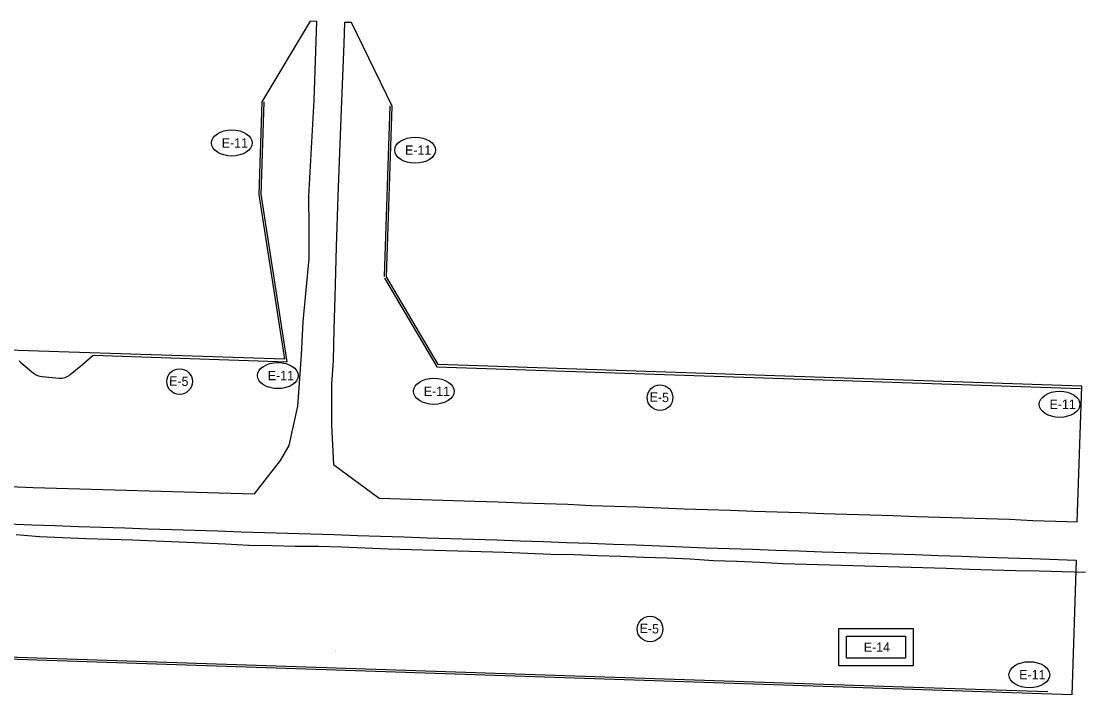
# Model space of a CAD drawing. Extents: x 977239 to 983725, y 1525948 to 1526901.
# Drawn here: x 978169 to 978854, y 1526369 to 1526803 of the extents above; entities that cross this region are included whole.
import ezdxf

# ---------------------------------------------------------------- set-up
doc = ezdxf.new("R2010")
doc.units = 0
for name, color, linetype in [('R_Erosion', 7, 'Continuous'), ('R_No Plot', 7, 'Continuous'), ('R_Water', 7, 'Continuous')]:
    doc.layers.add(name, color=color, linetype=linetype)

msp = doc.modelspace()

# ---------------------------------------------------------------- linework, layer by layer
at = {"layer": 'R_Erosion'}
for p, q in [((978323.31, 1526691.17), (978325.31, 1526751.13)), ((978406.27, 1526748.43), (978402.59, 1526638.49)), ((978340.18, 1526583.6), (978323.29, 1526691.54)), ((978402.87, 1526637.4), (978436.57, 1526580.37)), ((978168.64, 1526582.83), (978176.48, 1526576.28)), ((978215.04, 1526587.8), (978340.18, 1526583.6)), ((978200.27, 1526575.28), (978208.1, 1526581.74)), ((978436.57, 1526580.37), (978851.75, 1526566.46)), ((978182.02, 1526574), (978193.03, 1526573.03)), ((978128.43, 1526394.59), (978743.95, 1526373.96)), ((978743.95, 1526373.96), (978830.77, 1526371.05))]:
    msp.add_line(p, q, dxfattribs=at)
msp.add_lwpolyline([(978208.32, 1526581.93), (978215.04, 1526587.8)], dxfattribs=at)
for points in [[(978695.81, 1526411.68), (978743.81, 1526411.7), (978743.81, 1526387.7), (978695.81, 1526387.68)], [(978700.81, 1526406.68), (978738.81, 1526406.7), (978738.81, 1526392.7), (978700.81, 1526392.68)]]:
    msp.add_lwpolyline(points, close=True, dxfattribs=at)
for centre in [(978270.74, 1526570.81), (978580.61, 1526560.44), (978574.17, 1526411.38)]:
    msp.add_circle(centre, 8.26, dxfattribs=at)
for centre, start, end in [((978175.04, 1526590.51), 218.29041, 230.15852), ((978182.89, 1526583.96), 230.15852, 264.99974), ((978201.74, 1526589.46), 309.51371, 311.152), ((978193.91, 1526583), 264.99974, 309.51371)]:
    msp.add_arc(centre, 10, start, end, dxfattribs=at)
for centre in [(978304.42, 1526724.55), (978422.62, 1526719.89), (978334.1, 1526574.66), (978434.71, 1526564.55), (978838.25, 1526556.17), (978818.73, 1526381.9)]:
    msp.add_ellipse(centre, major_axis=(13.15, 0), ratio=0.638788, dxfattribs=at)
at = {"layer": 'R_No Plot'}
for p, q in [((978355.02, 1526802.97), (978323.81, 1526751.05)), ((978359.16, 1526802.84), (978355.02, 1526802.97)), ((978381.56, 1526802.09), (978377.18, 1526802.23)), ((978407.76, 1526748.25), (978381.56, 1526802.09)), ((978323.81, 1526751.05), (978321.81, 1526691.26)), ((978404.09, 1526638.29), (978407.76, 1526748.25)), ((978321.81, 1526691.26), (978338.42, 1526585.16)), ((978437.45, 1526581.84), (978404.09, 1526638.29)), ((978338.42, 1526585.16), (978136.55, 1526591.93)), ((978852.61, 1526567.93), (978437.45, 1526581.84)), ((978849.68, 1526480.46), (978852.61, 1526567.93)), ((978161.38, 1526503.3), (978176.36, 1526502.64)), ((978176.36, 1526502.64), (978191.36, 1526502.23)), ((978191.36, 1526502.23), (978206.35, 1526501.67)), ((978206.35, 1526501.67), (978221.34, 1526501.21)), ((978221.34, 1526501.21), (978236.2, 1526500.8)), ((978236.2, 1526500.8), (978251.19, 1526500.38)), ((978251.19, 1526500.38), (978266.19, 1526499.97)), ((978266.19, 1526499.97), (978281.18, 1526499.46)), ((978281.18, 1526499.46), (978319.1, 1526498.58)), ((978399.47, 1526495.75), (978461.18, 1526493.66)), ((978461.18, 1526493.66), (978476.18, 1526493.23)), ((978476.18, 1526493.23), (978491.17, 1526492.72)), ((978491.17, 1526492.72), (978506.16, 1526492.22)), ((978506.16, 1526492.22), (978521.15, 1526491.72)), ((978521.15, 1526491.72), (978536.14, 1526491.07)), ((978536.14, 1526491.07), (978551.13, 1526490.56)), ((978551.13, 1526490.56), (978566.12, 1526490.06)), ((978566.12, 1526490.06), (978581.11, 1526489.47)), ((978581.11, 1526489.47), (978596.14, 1526488.92)), ((978596.14, 1526488.92), (978611.13, 1526488.49)), ((978611.13, 1526488.49), (978626.12, 1526487.94)), ((978626.12, 1526487.94), (978641.11, 1526487.37)), ((978641.11, 1526487.37), (978656.11, 1526486.91)), ((978656.11, 1526486.91), (978671.1, 1526486.38)), ((978671.1, 1526486.38), (978686.02, 1526485.87)), ((978686.02, 1526485.87), (978701.01, 1526485.39)), ((978701.01, 1526485.39), (978716, 1526484.91)), ((978716, 1526484.91), (978731, 1526484.43)), ((978731, 1526484.43), (978745.99, 1526483.96)), ((978745.99, 1526483.96), (978760.98, 1526483.48)), ((978760.98, 1526483.48), (978775.97, 1526483)), ((978775.97, 1526483), (978790.96, 1526482.53)), ((978790.96, 1526482.53), (978805.96, 1526482.06)), ((978805.96, 1526482.06), (978820.94, 1526481.37)), ((978820.94, 1526481.37), (978835.93, 1526480.9)), ((978835.93, 1526480.9), (978849.68, 1526480.46)), ((978160.49, 1526479.09), (978175.48, 1526478.58)), ((978175.48, 1526478.58), (978190.47, 1526478.02)), ((978190.47, 1526478.02), (978205.46, 1526477.46)), ((978205.46, 1526477.46), (978220.45, 1526476.94)), ((978220.45, 1526476.94), (978235.54, 1526476.48)), ((978235.54, 1526476.48), (978250.54, 1526476.02)), ((978250.54, 1526476.02), (978265.53, 1526475.57)), ((978265.53, 1526475.57), (978280.52, 1526475.09)), ((978280.52, 1526475.09), (978295.51, 1526474.59)), ((978295.51, 1526474.59), (978310.5, 1526474.06)), ((978310.5, 1526474.06), (978325.48, 1526473.61)), ((978325.48, 1526473.61), (978340.47, 1526473.18)), ((978340.47, 1526473.18), (978355.46, 1526472.68)), ((978355.46, 1526472.68), (978370.45, 1526472.2)), ((978165.3, 1526472.32), (978180.33, 1526470.98)), ((978180.33, 1526470.98), (978195.33, 1526470.34)), ((978195.33, 1526470.34), (978210.32, 1526469.79)), ((978210.32, 1526469.79), (978225.48, 1526469.34)), ((978225.48, 1526469.34), (978240.47, 1526468.89)), ((978240.47, 1526468.89), (978255.46, 1526468.15)), ((978255.46, 1526468.15), (978270.45, 1526467.52)), ((978270.45, 1526467.52), (978285.44, 1526467.01)), ((978285.44, 1526467.01), (978300.41, 1526466.17)), ((978300.41, 1526466.17), (978315.37, 1526465.37)), ((978370.45, 1526472.2), (978385.38, 1526471.71)), ((978385.38, 1526471.71), (978400.37, 1526471.18)), ((978400.37, 1526471.18), (978415.36, 1526470.67)), ((978415.36, 1526470.67), (978430.37, 1526470.16)), ((978430.37, 1526470.16), (978445.36, 1526469.71)), ((978445.36, 1526469.71), (978460.35, 1526469.22)), ((978460.35, 1526469.22), (978475.35, 1526468.75)), ((978475.35, 1526468.75), (978490.34, 1526468.23)), ((978490.34, 1526468.23), (978505.33, 1526467.68)), ((978505.33, 1526467.68), (978520.32, 1526467.18)), ((978520.32, 1526467.18), (978535.31, 1526466.67)), ((978535.31, 1526466.67), (978550.3, 1526466.12)), ((978550.3, 1526466.12), (978565.29, 1526465.55)), ((978315.37, 1526465.37), (978330.38, 1526465.16)), ((978330.38, 1526465.16), (978345.37, 1526464.79)), ((978345.37, 1526464.79), (978360.38, 1526464.68)), ((978360.38, 1526464.68), (978375.24, 1526464.28)), ((978375.24, 1526464.28), (978390.22, 1526463.65)), ((978390.22, 1526463.65), (978405.22, 1526463.13)), ((978405.22, 1526463.13), (978420.24, 1526462.59)), ((978420.24, 1526462.59), (978435.24, 1526462.23)), ((978435.24, 1526462.23), (978450.23, 1526461.78)), ((978450.23, 1526461.78), (978465.22, 1526461.26)), ((978465.22, 1526461.26), (978480.22, 1526460.81)), ((978480.22, 1526460.81), (978495.2, 1526460.23)), ((978495.2, 1526460.23), (978510.19, 1526459.55)), ((978510.19, 1526459.55), (978525.2, 1526459.29)), ((978525.2, 1526459.29), (978540.18, 1526458.84)), ((978565.29, 1526465.55), (978580.28, 1526464.96)), ((978580.28, 1526464.96), (978595.23, 1526464.35)), ((978595.23, 1526464.35), (978610.22, 1526463.74)), ((978610.22, 1526463.74), (978625.22, 1526463.26)), ((978625.22, 1526463.26), (978640.21, 1526462.74)), ((978640.21, 1526462.74), (978655.2, 1526462.19)), ((978655.2, 1526462.19), (978670.19, 1526461.69)), ((978670.19, 1526461.69), (978685.23, 1526461.19)), ((978685.23, 1526461.19), (978700.23, 1526460.71)), ((978700.23, 1526460.71), (978715.22, 1526460.23)), ((978715.22, 1526460.23), (978730.21, 1526459.78)), ((978730.21, 1526459.78), (978745.2, 1526459.32)), ((978745.2, 1526459.32), (978760.19, 1526458.8)), ((978540.18, 1526458.84), (978555.17, 1526458.27)), ((978555.17, 1526458.27), (978570.16, 1526457.71)), ((978570.16, 1526457.71), (978585.1, 1526457.17)), ((978585.1, 1526457.17), (978600.07, 1526456.51)), ((978600.07, 1526456.51), (978615.05, 1526455.48)), ((978615.05, 1526455.48), (978630.05, 1526455.08)), ((978630.05, 1526455.08), (978645.03, 1526454.37)), ((978645.03, 1526454.37), (978660.02, 1526453.65)), ((978660.02, 1526453.65), (978675.02, 1526453.22)), ((978675.02, 1526453.22), (978690.11, 1526452.72)), ((978690.11, 1526452.72), (978705.1, 1526452.39)), ((978705.1, 1526452.39), (978720.09, 1526451.92)), ((978760.19, 1526458.8), (978775.18, 1526458.23)), ((978775.18, 1526458.23), (978790.18, 1526457.73)), ((978790.18, 1526457.73), (978805.17, 1526457.26)), ((978805.17, 1526457.26), (978820.17, 1526456.76)), ((978820.17, 1526456.76), (978848.97, 1526455.83)), ((978848.97, 1526455.83), (978846.06, 1526369.04)), ((978720.09, 1526451.92), (978735.09, 1526451.52)), ((978735.09, 1526451.52), (978750.08, 1526451.05)), ((978750.08, 1526451.05), (978765.07, 1526450.59)), ((978765.07, 1526450.59), (978780.07, 1526450.03)), ((978780.07, 1526450.03), (978795.07, 1526449.59)), ((978795.07, 1526449.59), (978810.06, 1526449.11)), ((978810.06, 1526449.11), (978825.06, 1526448.88)), ((978825.06, 1526448.88), (978840.06, 1526448.5)), ((978840.06, 1526448.5), (978855.05, 1526447.99)), ((978846.06, 1526369.04), (978129.88, 1526393.04))]:
    msp.add_line(p, q, dxfattribs=at)
for points in [[(978319.1, 1526498.58), (978335.91, 1526519.98), (978341.44, 1526529.58), (978344.21, 1526542.22), (978346.98, 1526554.9), (978349.45, 1526587.84), (978350.46, 1526609.55), (978354.4, 1526649.88), (978354.29, 1526670.11), (978354.18, 1526690.37), (978355.02, 1526705.82), (978355.86, 1526721.25), (978356.7, 1526736.68), (978357.54, 1526752.11), (978359.16, 1526802.84)], [(978377.18, 1526802.23), (978376.62, 1526788.73), (978375.96, 1526772.77), (978375.29, 1526756.81), (978374.63, 1526740.85), (978372.73, 1526690.21), (978371.8, 1526657.7), (978371.33, 1526641.44), (978370.86, 1526625.18), (978370.29, 1526604.84), (978369.73, 1526584.49), (978368.76, 1526569.04), (978368.69, 1526542.8), (978370.02, 1526517.36), (978399.47, 1526495.75)]]:
    msp.add_lwpolyline(points, dxfattribs=at)
for centre in [(978270.74, 1526570.81), (978580.61, 1526560.44), (978574.17, 1526411.38)]:
    msp.add_circle(centre, 8.26, dxfattribs=at)
for centre in [(978304.42, 1526724.55), (978422.62, 1526719.89), (978334.1, 1526574.66), (978434.71, 1526564.55)]:
    msp.add_ellipse(centre, major_axis=(13.15, 0), ratio=0.638788, dxfattribs=at)

# ---------------------------------------------------------------- texts
at = {"layer": 'R_Erosion'}
for p in [(978297.92, 1526721.6), (978416.12, 1526716.94), (978327.6, 1526571.71), (978428.21, 1526561.6), (978831.75, 1526553.22), (978812.23, 1526378.95)]:
    msp.add_text('E-11', height=5.999, dxfattribs=at).set_placement(p)
for s, height, rotation, p in [('E-5 ', 5.999, 358.09005, (978263.89, 1526568.31)), ('E-5 ', 5.999, 358.09005, (978573.77, 1526557.94)), ('E-5 ', 5.999, 358.09005, (978567.33, 1526408.88)), ('E-14', 6, 0.01643, (978711.97, 1526396.69))]:
    msp.add_text(s, height=height, rotation=rotation, dxfattribs=at).set_placement(p)
at = {"layer": 'R_Water'}
for rotation, p in [(359.26731, (978650.33, 1526524.61)), (358.97524, (978370.91, 1526397.11))]:
    msp.add_text('CONST. LIMITS', height=0.12, rotation=rotation, dxfattribs=at).set_placement(p)

doc.saveas('drawing.dxf')
